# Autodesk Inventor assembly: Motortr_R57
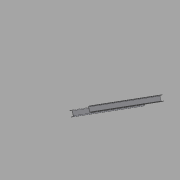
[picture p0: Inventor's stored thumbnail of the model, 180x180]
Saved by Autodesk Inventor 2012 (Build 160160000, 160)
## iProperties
Company: CAD-Verlag
Created: 2004-09
Part Number: Motortr_R57
Document SubType Name: Assembly
Designer: Greiling
Manufacturer: Standard
Standards Organization: Custom
Control State: 0
Master: False
Checked Out: False
Shininess: 64.0
Length Units: 11269
Angle Units: 11279
Time Units: 11290
Mass Units: 11283
Length Display Precision: 3
Angle Display Precision: 2
Compacted: True
Density: 0.0
Volumn: 0.0
Area: 0.0
PropertySet Name: Model Information
Author: Jürgen Kronas
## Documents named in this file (3)
- C:\DemoDaten2012\CAD Daten\Daten Vault 2012 Inventor\Kapitel 6\6.4\Rollenbahn\Rollenbahn 1400\Motortr_R57.iam
- C:\DemoDaten2012\CAD Daten\Daten Vault 2012 Inventor\Kapitel 6\6.4\Rollenbahn\Rollenbahn 1400\U100505_1637.ipt
- C:\DemoDaten2012\CAD Daten\Daten Vault 2012 Inventor\Kapitel 6\6.4\Rollenbahn\Rollenbahn 1400\MotorplR57.ipt
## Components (3 placed, 2 different names)
1. U100505_1637:1 — Passend:1, Fluchtend:1, Fluchtend:4
2. U100505_1637:2 — Fluchtend:2, Passend:2, Fluchtend:3, Fluchtend:4
3. MotorplR57:1 — Passend:1, Fluchtend:1, Fluchtend:2, Passend:2, Fluchtend:3
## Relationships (6: Flush 4, Mate 2)
- Passend:1 [Mate]: U100505_1637:1 ↔ MotorplR57:1
- Fluchtend:1 [Flush]: U100505_1637:1 ↔ MotorplR57:1
- Fluchtend:2 [Flush]: U100505_1637:2 ↔ MotorplR57:1
- Passend:2 [Mate]: U100505_1637:2 ↔ MotorplR57:1
- Fluchtend:3 [Flush]: U100505_1637:2 ↔ MotorplR57:1
- Fluchtend:4 [Flush]: U100505_1637:1 ↔ U100505_1637:2
